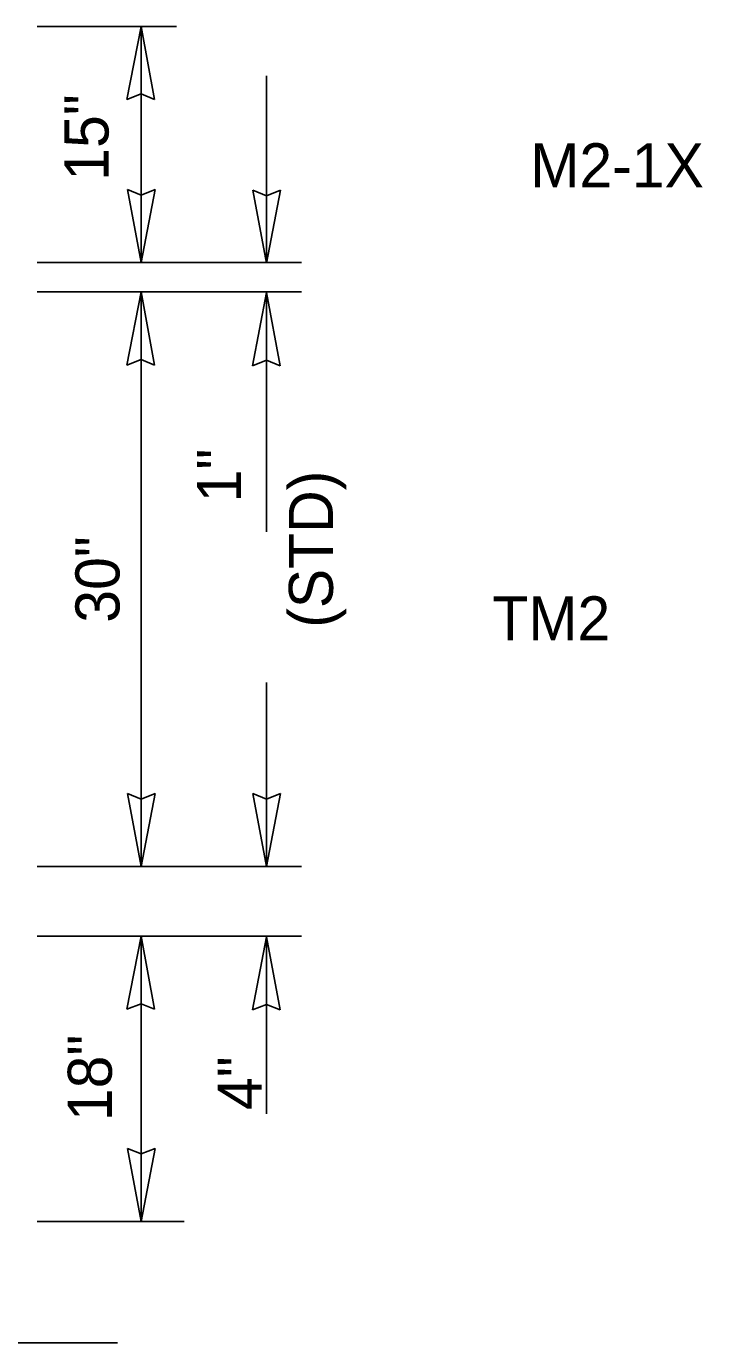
# Model space of a CAD drawing. Extents: x 52649 to 53276, y 9410 to 9805.
# Drawn here: x 52780.2 to 52820.5, y 9645.1 to 9723.5 of the extents above; entities that cross this region are included whole.
import ezdxf

# ---------------------------------------------------------------- set-up
doc = ezdxf.new("R2010")
doc.units = 0
doc.layers.add('DimLines_dp', color=7, linetype='Continuous')

msp = doc.modelspace()

# ---------------------------------------------------------------- linework, layer by layer
at = {"layer": 'DimLines_dp'}
for p, q in [((52789.181, 9723.469), (52780.885, 9723.469)), ((52787.067, 9723.469), (52786.227, 9719.119)), ((52787.067, 9723.469), (52786.227, 9719.119)), ((52787.067, 9723.469), (52787.067, 9709.395)), ((52787.877, 9719.119), (52787.067, 9723.469)), ((52787.877, 9719.119), (52787.067, 9723.469)), ((52794.535, 9720.523), (52794.535, 9709.355)), ((52786.227, 9719.119), (52787.067, 9719.449)), ((52786.227, 9719.119), (52787.067, 9719.449)), ((52787.067, 9719.449), (52787.877, 9719.119)), ((52787.067, 9719.449), (52787.877, 9719.119)), ((52787.067, 9713.415), (52786.257, 9713.745)), ((52786.257, 9713.745), (52787.067, 9709.395)), ((52787.067, 9713.415), (52786.257, 9713.745)), ((52786.257, 9713.745), (52787.067, 9709.395)), ((52787.067, 9709.395), (52787.907, 9713.745)), ((52787.907, 9713.745), (52787.067, 9713.415)), ((52787.067, 9709.395), (52787.907, 9713.745)), ((52787.907, 9713.745), (52787.067, 9713.415)), ((52794.535, 9713.375), (52793.725, 9713.705)), ((52793.725, 9713.705), (52794.535, 9709.355)), ((52794.535, 9713.375), (52793.725, 9713.705)), ((52793.725, 9713.705), (52794.535, 9709.355)), ((52794.535, 9709.355), (52795.375, 9713.705)), ((52795.375, 9713.705), (52794.535, 9713.375)), ((52794.535, 9709.355), (52795.375, 9713.705)), ((52795.375, 9713.705), (52794.535, 9713.375)), ((52796.613, 9709.395), (52780.885, 9709.395)), ((52796.613, 9707.645), (52780.885, 9707.645)), ((52787.067, 9707.645), (52786.227, 9703.295)), ((52787.067, 9707.645), (52786.227, 9703.295)), ((52787.067, 9707.645), (52787.067, 9673.417)), ((52787.877, 9703.295), (52787.067, 9707.645)), ((52787.877, 9703.295), (52787.067, 9707.645)), ((52794.535, 9707.605), (52793.695, 9703.255)), ((52794.535, 9707.605), (52793.695, 9703.255)), ((52794.535, 9707.605), (52794.535, 9693.365)), ((52795.345, 9703.255), (52794.535, 9707.605)), ((52795.345, 9703.255), (52794.535, 9707.605)), ((52786.227, 9703.295), (52787.067, 9703.625)), ((52786.227, 9703.295), (52787.067, 9703.625)), ((52787.067, 9703.625), (52787.877, 9703.295)), ((52787.067, 9703.625), (52787.877, 9703.295)), ((52793.695, 9703.255), (52794.535, 9703.585)), ((52793.695, 9703.255), (52794.535, 9703.585)), ((52794.535, 9703.585), (52795.345, 9703.255)), ((52794.535, 9703.585), (52795.345, 9703.255)), ((52794.535, 9684.379), (52794.535, 9673.417)), ((52787.067, 9677.437), (52786.257, 9677.767)), ((52786.257, 9677.767), (52787.067, 9673.417)), ((52787.067, 9677.437), (52786.257, 9677.767)), ((52786.257, 9677.767), (52787.067, 9673.417)), ((52787.067, 9673.417), (52787.907, 9677.767)), ((52787.907, 9677.767), (52787.067, 9677.437)), ((52787.067, 9673.417), (52787.907, 9677.767)), ((52787.907, 9677.767), (52787.067, 9677.437)), ((52794.535, 9677.437), (52793.725, 9677.767)), ((52793.725, 9677.767), (52794.535, 9673.417)), ((52794.535, 9677.437), (52793.725, 9677.767)), ((52793.725, 9677.767), (52794.535, 9673.417)), ((52794.535, 9673.417), (52795.375, 9677.767)), ((52795.375, 9677.767), (52794.535, 9677.437)), ((52794.535, 9673.417), (52795.375, 9677.767)), ((52795.375, 9677.767), (52794.535, 9677.437)), ((52796.613, 9673.417), (52780.885, 9673.417)), ((52796.613, 9669.271), (52780.885, 9669.271)), ((52787.067, 9669.271), (52786.227, 9664.921)), ((52787.067, 9669.271), (52786.227, 9664.921)), ((52787.067, 9669.271), (52787.067, 9652.287)), ((52787.877, 9664.921), (52787.067, 9669.271)), ((52787.877, 9664.921), (52787.067, 9669.271)), ((52794.535, 9669.231), (52793.695, 9664.881)), ((52794.535, 9669.231), (52793.695, 9664.881)), ((52794.535, 9669.231), (52794.535, 9658.685)), ((52795.345, 9664.881), (52794.535, 9669.231)), ((52795.345, 9664.881), (52794.535, 9669.231)), ((52786.227, 9664.921), (52787.067, 9665.251)), ((52786.227, 9664.921), (52787.067, 9665.251)), ((52787.067, 9665.251), (52787.877, 9664.921)), ((52787.067, 9665.251), (52787.877, 9664.921)), ((52793.695, 9664.881), (52794.535, 9665.211)), ((52793.695, 9664.881), (52794.535, 9665.211)), ((52794.535, 9665.211), (52795.345, 9664.881)), ((52794.535, 9665.211), (52795.345, 9664.881)), ((52787.067, 9656.307), (52786.257, 9656.637)), ((52786.257, 9656.637), (52787.067, 9652.287)), ((52787.067, 9656.307), (52786.257, 9656.637)), ((52786.257, 9656.637), (52787.067, 9652.287)), ((52787.067, 9652.287), (52787.907, 9656.637)), ((52787.907, 9656.637), (52787.067, 9656.307)), ((52787.067, 9652.287), (52787.907, 9656.637)), ((52787.907, 9656.637), (52787.067, 9656.307)), ((52789.641, 9652.287), (52780.885, 9652.287)), ((52785.669, 9645.061), (52775.239, 9645.061))]:
    msp.add_line(p, q, dxfattribs=at)

# ---------------------------------------------------------------- texts
for s, p in [('15"', (52785.133, 9714.272)), ('1"', (52793.026, 9695.116)), ('(STD)', (52798.492, 9687.644)), ('30"', (52785.784, 9687.946)), ('18"', (52785.328, 9658.257)), ('4"', (52794.249, 9658.917))]:
    msp.add_text(s, height=2.625, rotation=90, dxfattribs=at).set_placement(p)
for s, p in [('M2-1X', (52810.242, 9713.878)), ('TM2', (52807.983, 9686.892))]:
    msp.add_text(s, height=2.625, dxfattribs=at).set_placement(p)

doc.saveas('drawing.dxf')
